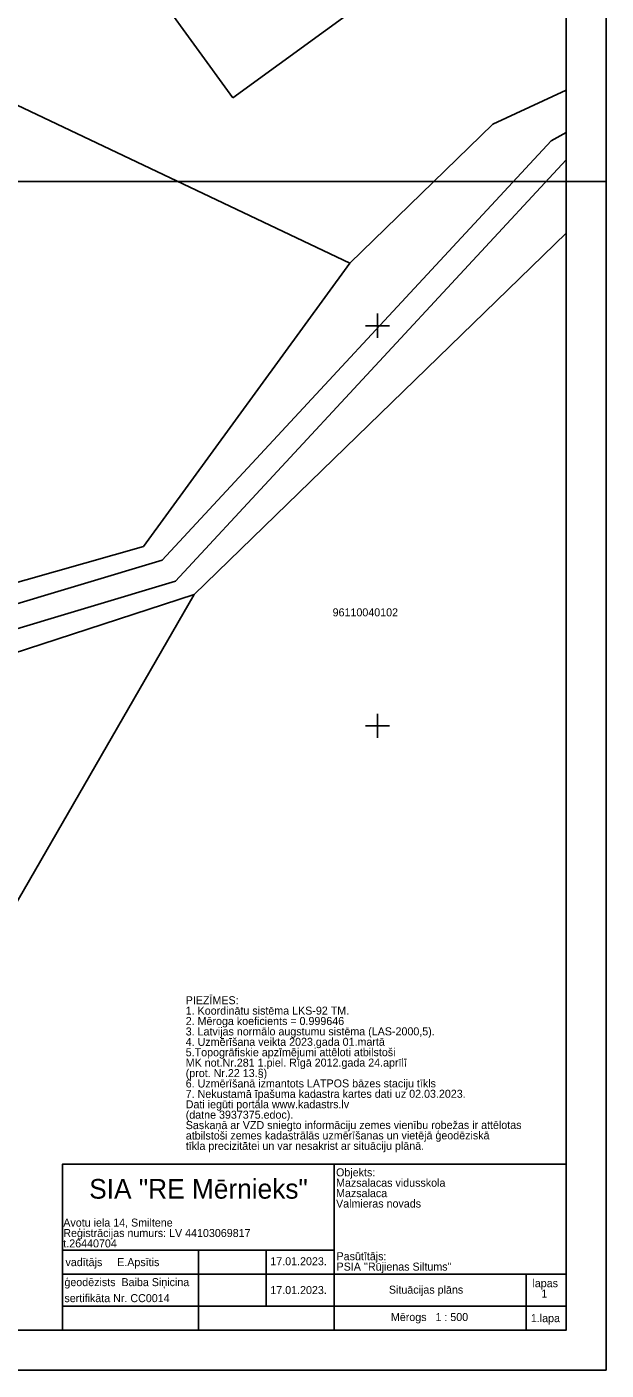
# Model space of a CAD drawing. Extents: x 561134 to 561329, y 413819 to 414116.
# Drawn here: x 561256.1 to 561328.6, y 413819.5 to 413987.3 of the extents above; entities that cross this region are included whole.
import ezdxf

# ---------------------------------------------------------------- set-up
doc = ezdxf.new("R2010")
doc.units = 0
for name, color, linetype in [('BUVE_EKAS_UZMR_####_#', 7, 'Continuous'), ('BUVE_INZE_VEKT_####_#', 7, 'Continuous'), ('GEOD_ELEM_####_####_#', 7, 'Continuous'), ('RAMI_PLAN_####_TKST_#', 7, 'Continuous'), ('ROBZ_UZMR_####_####_#', 7, 'Continuous'), ('ROBZ_UZMR_####_TKST_#', 7, 'Continuous')]:
    doc.layers.add(name, color=color, linetype=linetype)

msp = doc.modelspace()

# ---------------------------------------------------------------- linework, layer by layer
at = {"layer": 'BUVE_EKAS_UZMR_####_#'}
for p, q in [((561306.59, 413996.43), (561281.89, 413978.48)), ((561281.89, 413978.48), (561272.79, 413991.01))]:
    msp.add_line(p, q, dxfattribs=at)
at = {"layer": 'BUVE_INZE_VEKT_####_#'}
for p, q in [((561321.7, 413973.1), (561323.58, 413974.14)), ((561273.06, 413920.72), (561321.7, 413973.1)), ((561323.57, 413970.71), (561274.71, 413918.09)), ((561323.58, 413970.71), (561323.57, 413970.71)), ((561207.26, 413900.89), (561273.06, 413920.72)), ((561274.71, 413918.09), (561207.98, 413897.97))]:
    msp.add_line(p, q, dxfattribs=at)
at = {"layer": 'GEOD_ELEM_####_####_#'}
for p, q in [((561298.5, 413950), (561300, 413950)), ((561300, 413951.5), (561300, 413950)), ((561300, 413950), (561300, 413948.5)), ((561300, 413950), (561301.5, 413950)), ((561300, 413901.5), (561300, 413900)), ((561298.5, 413900), (561300, 413900)), ((561300, 413900), (561300, 413898.5)), ((561300, 413900), (561301.5, 413900))]:
    msp.add_line(p, q, dxfattribs=at)
at = {"layer": 'RAMI_PLAN_####_TKST_#'}
for p, q in [((561328.58, 413968), (561328.58, 414116.5)), ((561328.58, 413968), (561133.58, 413968)), ((561328.58, 413819.5), (561328.58, 413968)), ((561260.58, 413834.49), (561294.58, 413834.5)), ((561277.58, 413824.5), (561277.58, 413834.5)), ((561286.08, 413827.5), (561286.08, 413834.5)), ((561260.58, 413831.5), (561294.58, 413831.5)), ((561318.58, 413831.5), (561318.58, 413824.5)), ((561323.58, 413824.5), (561323.58, 413831.5)), ((561260.58, 413827.49), (561294.58, 413827.5)), ((561294.58, 413827.5), (561318.58, 413827.5)), ((561318.58, 413827.5), (561323.58, 413827.5)), ((561294.58, 413824.5), (561323.58, 413824.5)), ((561328.58, 413819.5), (561133.58, 413819.5))]:
    msp.add_line(p, q, dxfattribs=at)
msp.add_lwpolyline([(561148.58, 414111.5), (561148.58, 413824.5), (561323.58, 413824.5), (561323.58, 414111.5)], close=True, dxfattribs=at)
for points in [[(561294.58, 413824.5), (561294.58, 413845.21), (561260.58, 413845.21), (561260.58, 413824.5), (561294.58, 413824.5)], [(561294.58, 413845.21), (561323.58, 413845.21), (561323.58, 413831.5), (561294.58, 413831.49), (561294.58, 413845.21)]]:
    msp.add_lwpolyline(points, dxfattribs=at)
at = {"layer": 'ROBZ_UZMR_####_####_#'}
for p, q in [((561296.51, 413957.82), (561148.58, 414028.03)), ((561323.58, 413979.44), (561314.39, 413975.18)), ((561314.39, 413975.18), (561296.51, 413957.82)), ((561277.05, 413916.42), (561323.58, 413961.56)), ((561296.51, 413957.82), (561270.72, 413922.39)), ((561270.72, 413922.39), (561195.12, 413901.02)), ((561220.11, 413897.84), (561277.05, 413916.42)), ((561277.05, 413916.42), (561236.89, 413846.84))]:
    msp.add_line(p, q, dxfattribs=at)

# ---------------------------------------------------------------- texts
at = {"layer": 'RAMI_PLAN_####_TKST_#'}
for s, height, rotation, p in [('PIEZĪMES:', 1, 0.0311, (561276, 413865.21)), ('1. Koordinātu sistēma LKS-92 TM.', 1, 0.0311, (561276, 413863.91)), ('2. Mēroga koeficients = 0.999646', 1, 0.0311, (561276, 413862.61)), ('4. Uzmērīšana veikta 2023.gada 01.martā', 1, 0.0311, (561276, 413860.01)), ('3. Latvijas normālo augstumu sistēma (LAS-2000,5).', 1, 0.0311, (561276, 413861.31)), ('5.Topogrāfiskie apzīmējumi attēloti atbilstoši', 1, 0.0311, (561276, 413858.71)), ('MK not.Nr.281 1.piel. Rīgā 2012.gada 24.aprīlī', 1, 0.0311, (561276, 413857.41)), ('(prot. Nr.22 13.§)', 1, 0.0311, (561276, 413856.11)), ('6. Uzmērīšanā izmantots LATPOS bāzes staciju tīkls', 1, 0.0311, (561276, 413854.81)), ('7. Nekustamā īpašuma kadastra kartes dati uz 02.03.2023.', 1, 0.0311, (561276, 413853.51)), ('Dati iegūti portāla www.kadastrs.lv ', 1, 0.0311, (561276, 413852.21)), ('(datne 3937375.edoc).', 1, 0.0311, (561276, 413850.91)), ('atbilstoši zemes kadastrālās uzmērīšanas un vietējā ģeodēziskā ', 1, 0.0311, (561276.01, 413848.31)), ('Saskaņā ar VZD sniegto informāciju zemes vienību robežas ir attēlotas ', 1, 0.0311, (561276, 413849.61)), ('tīkla precizitātei un var nesakrist ar situāciju plānā.', 1, 0.0311, (561276.01, 413847.01)), ('Objekts: ', 1, 359.9996, (561294.8, 413843.71)), ('SIA "RE Mērnieks"', 2.4559, 0.001, (561263.93, 413840.92)), ('Mazsalacas vidusskola', 1, 359.9996, (561294.8, 413842.41)), ('Valmieras novads', 1, 359.9996, (561294.8, 413839.81)), ('Mazsalaca', 1, 359.9996, (561294.8, 413841.11)), ('Avotu iela 14, Smiltene', 1, 0.001, (561260.69, 413837.43)), ('t.26440704', 1, 0.001, (561260.69, 413834.83)), ('Reģistrācijas numurs: LV 44103069817', 1, 0.001, (561260.69, 413836.13)), ('Pasūtītājs:', 1, 359.9996, (561294.86, 413833.23)), ('vadītājs     E.Apsītis', 1, 0.001, (561260.96, 413832.49)), ('17.01.2023.', 1, 0.001, (561286.58, 413832.6)), ("PSIA ''Rūjienas Siltums''", 1, 359.9996, (561294.86, 413831.93)), ('ģeodēzists  Baiba Siņicina', 1, 0.001, (561260.83, 413829.99)), ('lapas', 1, 0.001, (561319.36, 413829.86)), ('17.01.2023.', 1, 0.001, (561286.58, 413829)), ('Situācijas plāns', 1, 0.0007, (561301.41, 413829.05)), ('   1', 1, 0.001, (561319.36, 413828.56)), ('sertifikāta Nr. CC0014', 1, 0.001, (561260.83, 413827.99)), ('Mērogs   1 : 500', 1, 0.001, (561301.66, 413825.63)), ('1.lapa', 1, 0.001, (561319.16, 413825.49))]:
    msp.add_text(s, height=height, rotation=rotation, dxfattribs=at).set_placement(p)
at = {"layer": 'ROBZ_UZMR_####_TKST_#'}
msp.add_text('96110040102', height=1, dxfattribs=at).set_placement((561294.37, 413913.68))

doc.saveas('drawing.dxf')
